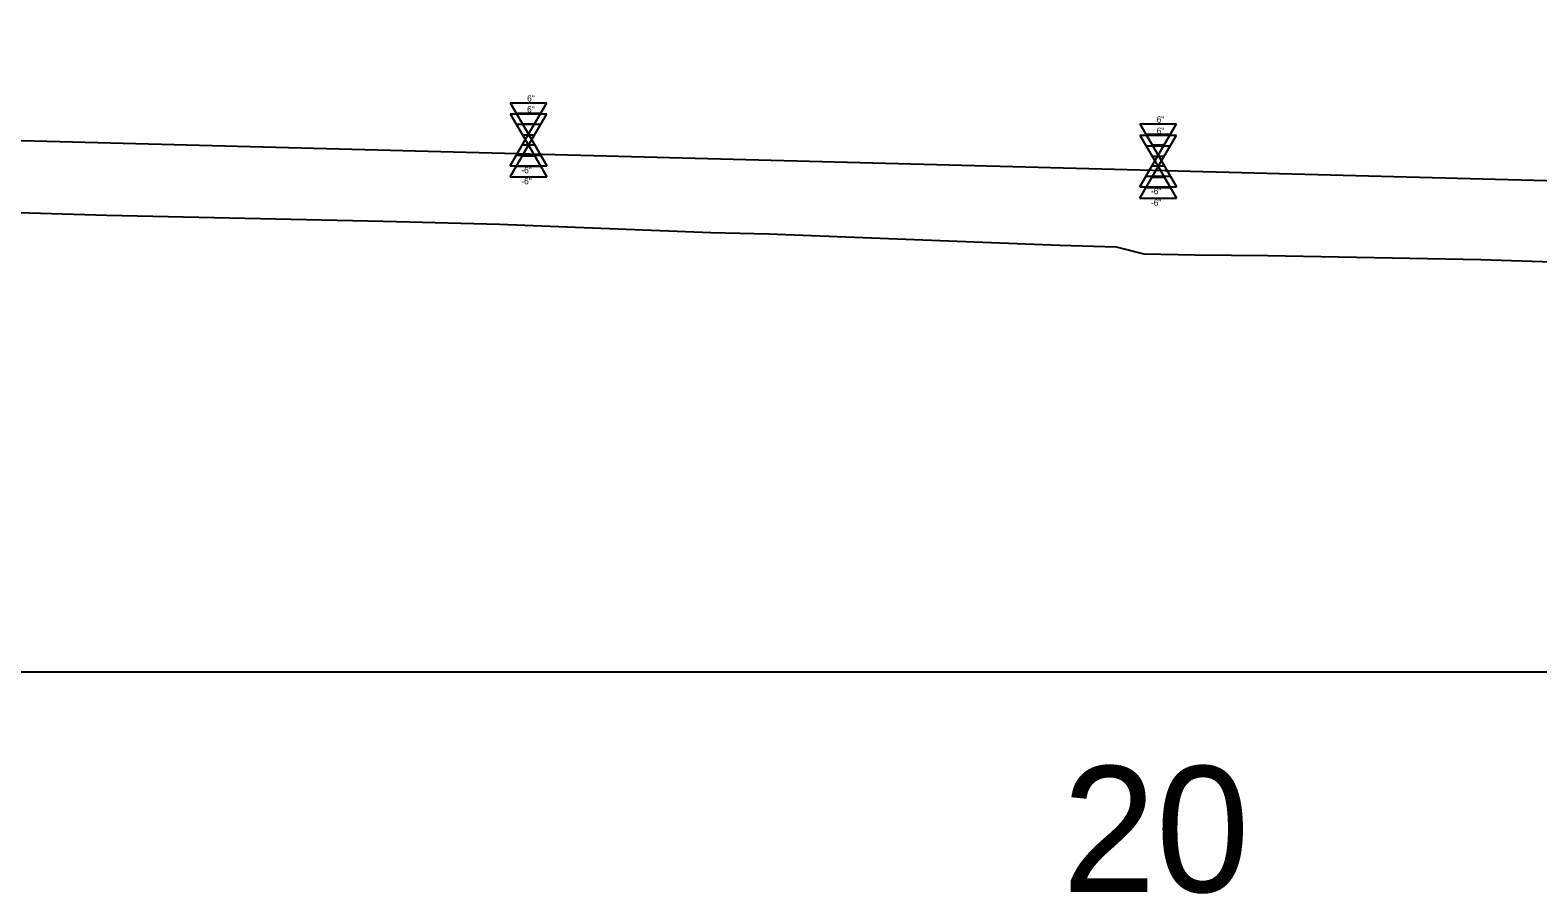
# Model space of a CAD drawing. Extents: x 573468 to 580768, y -57414 to -51768.
# Drawn here: x 574675.6 to 574795.4, y -53116.2 to -53047.5 of the extents above; entities that cross this region are included whole.
import ezdxf

# ---------------------------------------------------------------- set-up
doc = ezdxf.new("R2010")
doc.units = 0
for name, color, linetype in [('Exist Profile Cell', 7, 'Continuous'), ('Exist Vertical Profile Ground Line', 7, 'Continuous'), ('Exist Vertical Profile Horizontal Axis Label Major', 7, 'Continuous'), ('Pattern 2', 7, 'Continuous'), ('Prop Vertical Profile Grade', 7, 'Continuous'), ('Scratch_Level_0', 7, 'Continuous')]:
    doc.layers.add(name, color=color, linetype=linetype)

msp = doc.modelspace()

# ---------------------------------------------------------------- linework, layer by layer
at = {"layer": 'Exist Profile Cell'}
msp.add_line((573765.21, -53098.54), (577467.91, -53098.54), dxfattribs=at)
at = {"layer": 'Exist Vertical Profile Ground Line'}
msp.add_lwpolyline([(574673.81, -53062.02), (574681.74, -53062.26), (574703.67, -53062.73), (574704.74, -53062.76), (574712.92, -53062.97), (574729.69, -53063.62), (574734.29, -53063.74), (574757.42, -53064.64), (574761.88, -53064.77), (574764.07, -53065.32), (574768.16, -53065.4), (574773.92, -53065.45), (574790.85, -53065.78), (574805.44, -53066.25)], dxfattribs=at)
at = {"layer": 'Pattern 2'}
for p, q in [((574713.75, -53054.19), (574716.68, -53054.19)), ((574713.75, -53054.19), (574715.21, -53056.69)), ((574715.21, -53056.69), (574716.68, -53054.19)), ((574714.24, -53055.03), (574716.19, -53055.03)), ((574713.75, -53059.19), (574715.21, -53056.69)), ((574714.73, -53055.86), (574715.7, -53055.86)), ((574715.21, -53056.69), (574716.68, -53059.19)), ((574763.75, -53055.89), (574766.68, -53055.89)), ((574763.75, -53055.89), (574765.21, -53058.39)), ((574764.24, -53056.73), (574766.19, -53056.73)), ((574765.21, -53058.39), (574766.68, -53055.89)), ((574714.73, -53057.53), (574715.7, -53057.53)), ((574764.73, -53057.56), (574765.7, -53057.56)), ((574713.75, -53059.19), (574716.68, -53059.19)), ((574714.24, -53058.36), (574716.19, -53058.36)), ((574763.75, -53060.89), (574765.21, -53058.39)), ((574764.73, -53059.23), (574765.7, -53059.23)), ((574765.21, -53058.39), (574766.68, -53060.89)), ((574764.24, -53060.06), (574766.19, -53060.06)), ((574763.75, -53060.89), (574766.68, -53060.89))]:
    msp.add_line(p, q, dxfattribs=at)
at = {"layer": 'Prop Vertical Profile Grade'}
msp.add_line((574340.21, -53047.54), (574855.21, -53061.04), dxfattribs=at)
at = {"layer": 'Scratch_Level_0'}
for p, q in [((574713.75, -53053.32), (574716.68, -53053.32)), ((574713.75, -53053.32), (574715.21, -53055.82)), ((574715.21, -53055.82), (574716.68, -53053.32)), ((574714.24, -53054.15), (574716.19, -53054.15)), ((574714.73, -53054.99), (574715.7, -53054.99)), ((574763.75, -53054.99), (574766.68, -53054.99)), ((574763.75, -53054.99), (574765.21, -53057.49)), ((574765.21, -53057.49), (574766.68, -53054.99)), ((574713.75, -53058.32), (574715.21, -53055.82)), ((574714.73, -53056.65), (574715.7, -53056.65)), ((574715.21, -53055.82), (574716.68, -53058.32)), ((574764.24, -53055.82), (574766.19, -53055.82)), ((574764.73, -53056.66), (574765.7, -53056.66)), ((574714.24, -53057.49), (574716.19, -53057.49)), ((574763.75, -53059.99), (574765.21, -53057.49)), ((574765.21, -53057.49), (574766.68, -53059.99)), ((574713.75, -53058.32), (574716.68, -53058.32)), ((574764.24, -53059.16), (574766.19, -53059.16)), ((574764.73, -53058.32), (574765.7, -53058.32)), ((574763.75, -53059.99), (574766.68, -53059.99))]:
    msp.add_line(p, q, dxfattribs=at)

# ---------------------------------------------------------------- texts
at = {"layer": 'Exist Vertical Profile Horizontal Axis Label Major'}
msp.add_text('20', height=10, dxfattribs=at).set_placement((574757.6, -53116.04))
at = {"layer": 'Pattern 2'}
for s, p in [('6"', (574715.1, -53054.09)), ('6"', (574765.1, -53055.79)), ('-6"', (574714.64, -53059.8)), ('-6"', (574764.64, -53061.5))]:
    msp.add_text(s, height=0.5, rotation=360, dxfattribs=at).set_placement(p)
at = {"layer": 'Scratch_Level_0'}
for s, p in [('6"', (574715.1, -53053.22)), ('6"', (574765.1, -53054.89)), ('-6"', (574714.64, -53058.92)), ('-6"', (574764.64, -53060.59))]:
    msp.add_text(s, height=0.5, dxfattribs=at).set_placement(p)

doc.saveas('drawing.dxf')
